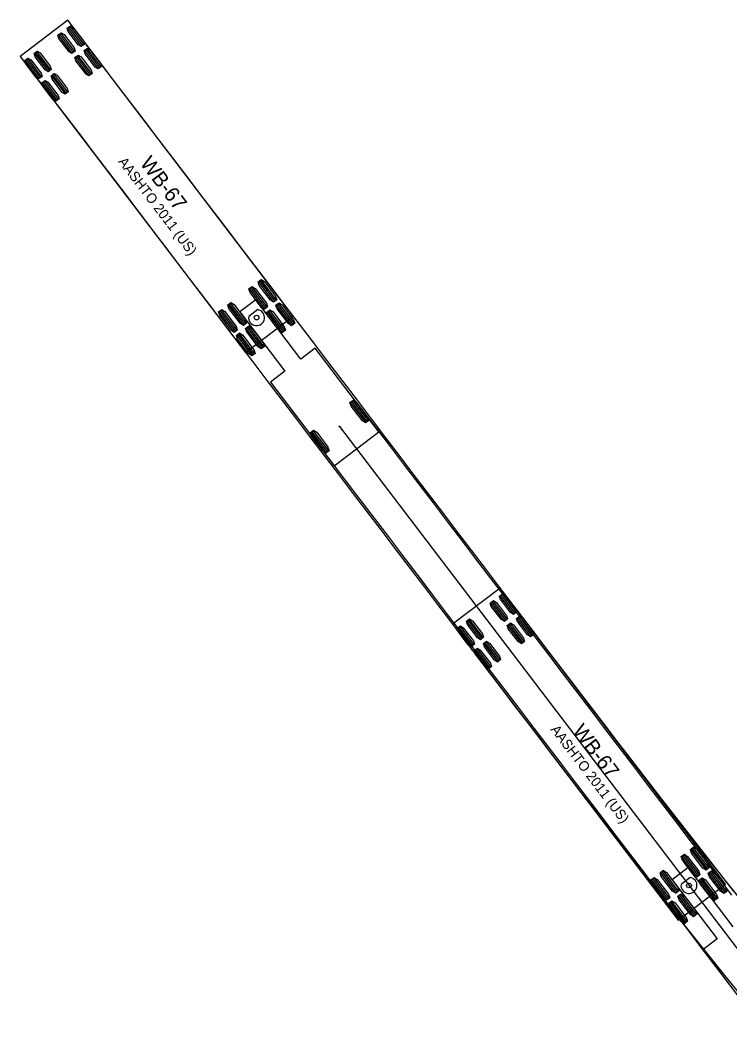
# Model space of a CAD drawing. Extents: x 916040 to 917457, y 328936 to 330267.
# Drawn here: x 916277.9 to 916379, y 330122.5 to 330266.8 of the extents above; entities that cross this region are included whole.
import ezdxf

# ---------------------------------------------------------------- set-up
doc = ezdxf.new("R2010")
doc.units = 0
for name, color, linetype in [('SB_LeftontoRoute25_WB67', 7, 'Continuous'), ('SB_RightontoRoute25_WB67_v2', 7, 'Continuous'), ('SB_ThruontonSacoRd_WB67', 7, 'Continuous')]:
    doc.layers.add(name, color=color, linetype=linetype)

msp = doc.modelspace()

# ---------------------------------------------------------------- linework, layer by layer
at = {"layer": 'SB_LeftontoRoute25_WB67'}
for p, q in [((916346.26, 330185.93), (916339.5, 330180.78)), ((916378.38, 330143.78), (916346.26, 330185.93)), ((916348.23, 330182.21), (916346.23, 330184.84)), ((916348.41, 330182.35), (916346.41, 330184.98)), ((916348.59, 330182.49), (916346.59, 330185.12)), ((916346.91, 330181.21), (916344.91, 330183.84)), ((916347.1, 330181.35), (916345.1, 330183.98)), ((916347.28, 330181.49), (916345.28, 330184.12)), ((916343.87, 330178.89), (916341.87, 330181.52)), ((916350.65, 330179.03), (916348.65, 330181.66)), ((916350.83, 330179.17), (916348.83, 330181.8)), ((916351.01, 330179.31), (916349.01, 330181.93)), ((916339.5, 330180.78), (916371.62, 330138.62)), ((916342.19, 330177.62), (916340.19, 330180.24)), ((916342.38, 330177.76), (916340.38, 330180.38)), ((916342.56, 330177.89), (916340.56, 330180.52)), ((916343.51, 330178.62), (916341.51, 330181.24)), ((916343.69, 330178.76), (916341.69, 330181.38)), ((916349.34, 330178.03), (916347.34, 330180.66)), ((916349.52, 330178.17), (916347.52, 330180.8)), ((916349.7, 330178.31), (916347.7, 330180.93)), ((916344.8, 330174.57), (916342.8, 330177.2)), ((916344.98, 330174.71), (916342.98, 330177.34)), ((916345.93, 330175.44), (916343.93, 330178.06)), ((916346.11, 330175.57), (916344.11, 330178.2)), ((916346.3, 330175.71), (916344.29, 330178.34)), ((916344.62, 330174.44), (916342.62, 330177.06)), ((916375.66, 330145.81), (916373.43, 330148.72)), ((916375.84, 330145.94), (916373.61, 330148.86)), ((916376.02, 330146.08), (916373.8, 330149)), ((916374.34, 330144.81), (916372.12, 330147.72)), ((916374.52, 330144.94), (916372.3, 330147.86)), ((916374.71, 330145.08), (916372.48, 330148)), ((916371.33, 330142.51), (916369.11, 330145.43)), ((916371.52, 330142.65), (916369.29, 330145.57)), ((916371.7, 330142.79), (916369.48, 330145.71)), ((916373.05, 330146.12), (916370.77, 330144.39)), ((916379.47, 330137.69), (916373.05, 330146.12)), ((916378.38, 330142.6), (916376.16, 330145.52)), ((916378.57, 330142.74), (916376.34, 330145.66)), ((916370.02, 330141.51), (916367.8, 330144.43)), ((916370.2, 330141.65), (916367.98, 330144.57)), ((916370.39, 330141.79), (916368.16, 330144.71)), ((916370.77, 330144.39), (916377.19, 330135.96)), ((916373.33, 330144.72), (916372.05, 330143.74)), ((916376.89, 330141.46), (916374.67, 330144.38)), ((916377.07, 330141.6), (916374.85, 330144.52)), ((916377.25, 330141.74), (916375.03, 330144.66)), ((916378.2, 330142.46), (916375.98, 330145.38)), ((916371.62, 330138.62), (916378.38, 330143.78)), ((916378.38, 330143.78), (916378.38, 330143.78)), ((916372.57, 330138.17), (916370.34, 330141.09)), ((916372.75, 330138.31), (916370.53, 330141.23)), ((916372.93, 330138.45), (916370.71, 330141.37)), ((916373.88, 330139.17), (916371.66, 330142.09)), ((916374.06, 330139.31), (916371.84, 330142.23)), ((916374.24, 330139.45), (916372.02, 330142.37)), ((916377.19, 330135.96), (916375.15, 330134.4)), ((916375.15, 330134.4), (916384.24, 330122.47))]:
    msp.add_line(p, q, dxfattribs=at)
for points in [[(916348.64, 330182.53), (916348.18, 330182.18), (916347.76, 330182.44), (916346.32, 330184.33), (916346.18, 330184.8), (916346.63, 330185.15), (916347.05, 330184.89), (916348.49, 330183)], [(916347.32, 330181.53), (916346.87, 330181.18), (916346.45, 330181.44), (916345.01, 330183.33), (916344.87, 330183.8), (916345.32, 330184.15), (916345.74, 330183.89), (916347.18, 330182)], [(916343.92, 330178.93), (916343.46, 330178.58), (916343.04, 330178.85), (916341.6, 330180.74), (916341.46, 330181.21), (916341.92, 330181.55), (916342.33, 330181.29), (916343.77, 330179.4)], [(916351.06, 330179.34), (916350.6, 330179), (916350.19, 330179.26), (916348.75, 330181.15), (916348.6, 330181.62), (916349.06, 330181.97), (916349.48, 330181.71), (916350.92, 330179.82)], [(916342.6, 330177.93), (916342.15, 330177.58), (916341.73, 330177.85), (916340.29, 330179.74), (916340.15, 330180.21), (916340.6, 330180.55), (916341.02, 330180.29), (916342.46, 330178.4)], [(916349.75, 330178.34), (916349.29, 330178), (916348.88, 330178.26), (916347.43, 330180.15), (916347.29, 330180.62), (916347.75, 330180.97), (916348.16, 330180.71), (916349.6, 330178.82)], [(916345.03, 330174.75), (916344.57, 330174.4), (916344.16, 330174.66), (916342.72, 330176.55), (916342.57, 330177.03), (916343.03, 330177.37), (916343.44, 330177.11), (916344.88, 330175.22)], [(916346.34, 330175.75), (916345.89, 330175.4), (916345.47, 330175.66), (916344.03, 330177.55), (916343.89, 330178.03), (916344.34, 330178.37), (916344.76, 330178.11), (916346.2, 330176.22)], [(916376.06, 330146.12), (916375.61, 330145.77), (916375.16, 330146.07), (916373.56, 330148.17), (916373.39, 330148.69), (916373.84, 330149.03), (916374.29, 330148.73), (916375.89, 330146.63)], [(916374.75, 330145.12), (916374.3, 330144.77), (916373.85, 330145.07), (916372.25, 330147.17), (916372.08, 330147.69), (916372.53, 330148.03), (916372.98, 330147.73), (916374.58, 330145.63)], [(916371.74, 330142.82), (916371.29, 330142.48), (916370.84, 330142.78), (916369.24, 330144.88), (916369.07, 330145.39), (916369.52, 330145.74), (916369.97, 330145.44), (916371.57, 330143.34)], [(916378.61, 330142.78), (916378.16, 330142.43), (916377.71, 330142.73), (916376.11, 330144.83), (916375.93, 330145.35), (916376.39, 330145.69), (916376.84, 330145.39), (916378.44, 330143.29)], [(916370.43, 330141.82), (916369.98, 330141.48), (916369.53, 330141.78), (916367.93, 330143.88), (916367.75, 330144.39), (916368.21, 330144.74), (916368.66, 330144.44), (916370.26, 330142.34)], [(916377.3, 330141.78), (916376.84, 330141.43), (916376.39, 330141.73), (916374.79, 330143.83), (916374.62, 330144.35), (916375.08, 330144.69), (916375.52, 330144.39), (916377.12, 330142.29)], [(916372.98, 330138.48), (916372.52, 330138.14), (916372.07, 330138.44), (916370.47, 330140.54), (916370.3, 330141.05), (916370.75, 330141.4), (916371.2, 330141.1), (916372.8, 330139)], [(916374.29, 330139.48), (916373.83, 330139.14), (916373.39, 330139.44), (916371.79, 330141.54), (916371.61, 330142.05), (916372.07, 330142.4), (916372.51, 330142.1), (916374.11, 330140)]]:
    msp.add_lwpolyline(points, close=True, dxfattribs=at)
for points in [[(916348.98, 330182.35), (916351.01, 330179.7), (916353.03, 330177.04), (916355.05, 330174.39), (916357.08, 330171.74), (916359.1, 330169.09), (916361.12, 330166.44), (916363.15, 330163.79), (916365.18, 330161.15), (916367.21, 330158.52), (916369.25, 330155.88), (916371.29, 330153.25), (916373.33, 330150.63), (916375.38, 330148.02), (916377.44, 330145.41), (916379.5, 330142.8)], [(916342.22, 330177.2), (916344.25, 330174.54), (916346.27, 330171.89), (916348.29, 330169.23), (916350.32, 330166.58), (916352.35, 330163.93), (916354.37, 330161.27), (916356.41, 330158.62), (916358.44, 330155.97), (916360.48, 330153.32), (916362.53, 330150.68), (916364.58, 330148.04), (916366.63, 330145.4), (916368.69, 330142.77), (916370.76, 330140.14), (916372.84, 330137.52), (916374.93, 330134.9), (916377.02, 330132.29), (916379.13, 330129.69)]]:
    msp.add_lwpolyline(points, dxfattribs=at)
for centre, radius in [((916348.98, 330182.35), 0.0417), ((916342.22, 330177.2), 0.0417), ((916373.18, 330143.59), 0.34)]:
    msp.add_circle(centre, radius, dxfattribs=at)
msp.add_arc((916373.18, 330143.59), 1.14, 172.3089, 82.3089, dxfattribs=at)
at = {"layer": 'SB_RightontoRoute25_WB67_v2'}
for p, q in [((916284.64, 330266.79), (916277.88, 330261.64)), ((916316.76, 330224.64), (916284.64, 330266.79)), ((916286.61, 330263.07), (916284.61, 330265.7)), ((916286.79, 330263.21), (916284.79, 330265.84)), ((916286.97, 330263.35), (916284.97, 330265.98)), ((916285.29, 330262.07), (916283.29, 330264.7)), ((916285.48, 330262.21), (916283.48, 330264.84)), ((916285.66, 330262.35), (916283.66, 330264.98)), ((916282.25, 330259.75), (916280.25, 330262.38)), ((916289.03, 330259.89), (916287.03, 330262.52)), ((916289.21, 330260.03), (916287.21, 330262.66)), ((916289.4, 330260.17), (916287.4, 330262.79)), ((916277.88, 330261.64), (916310, 330219.48)), ((916280.58, 330258.48), (916278.57, 330261.1)), ((916280.76, 330258.62), (916278.76, 330261.24)), ((916280.94, 330258.75), (916278.94, 330261.38)), ((916281.89, 330259.48), (916279.89, 330262.1)), ((916282.07, 330259.62), (916280.07, 330262.24)), ((916287.72, 330258.89), (916285.72, 330261.52)), ((916287.9, 330259.03), (916285.9, 330261.66)), ((916288.08, 330259.17), (916286.08, 330261.79)), ((916283.18, 330255.43), (916281.18, 330258.06)), ((916283.36, 330255.57), (916281.36, 330258.2)), ((916284.31, 330256.3), (916282.31, 330258.92)), ((916284.49, 330256.43), (916282.49, 330259.06)), ((916284.68, 330256.57), (916282.68, 330259.2)), ((916283, 330255.3), (916281, 330257.92)), ((916314.04, 330226.67), (916311.81, 330229.58)), ((916314.22, 330226.8), (916312, 330229.72)), ((916314.4, 330226.94), (916312.18, 330229.86)), ((916312.72, 330225.67), (916310.5, 330228.58)), ((916312.91, 330225.8), (916310.68, 330228.72)), ((916313.09, 330225.94), (916310.87, 330228.86)), ((916309.71, 330223.37), (916307.49, 330226.29)), ((916309.9, 330223.51), (916307.67, 330226.43)), ((916310.08, 330223.65), (916307.86, 330226.57)), ((916311.43, 330226.98), (916309.15, 330225.25)), ((916317.86, 330218.55), (916311.43, 330226.98)), ((916316.58, 330223.32), (916314.36, 330226.24)), ((916316.76, 330223.46), (916314.54, 330226.38)), ((916316.95, 330223.6), (916314.72, 330226.52)), ((916308.4, 330222.37), (916306.18, 330225.29)), ((916308.58, 330222.51), (916306.36, 330225.43)), ((916308.77, 330222.65), (916306.54, 330225.57)), ((916309.15, 330225.25), (916315.58, 330216.82)), ((916311.72, 330225.58), (916310.43, 330224.6)), ((916315.27, 330222.32), (916313.05, 330225.24)), ((916315.45, 330222.46), (916313.23, 330225.38)), ((916315.63, 330222.6), (916313.41, 330225.52)), ((916310, 330219.48), (916316.76, 330224.64)), ((916316.76, 330224.64), (916316.76, 330224.64)), ((916310.95, 330219.03), (916308.73, 330221.95)), ((916311.13, 330219.17), (916308.91, 330222.09)), ((916311.31, 330219.31), (916309.09, 330222.23)), ((916312.26, 330220.03), (916310.04, 330222.95)), ((916312.44, 330220.17), (916310.22, 330223.09)), ((916312.63, 330220.31), (916310.4, 330223.23)), ((916319.9, 330220.11), (916317.86, 330218.55)), ((916328.99, 330208.18), (916319.9, 330220.11)), ((916315.58, 330216.82), (916313.53, 330215.26)), ((916313.53, 330215.26), (916322.63, 330203.33)), ((916327.13, 330209.49), (916324.91, 330212.4)), ((916327.31, 330209.62), (916325.09, 330212.54)), ((916327.49, 330209.76), (916325.27, 330212.68)), ((916323.38, 330208.94), (916385, 330128.08)), ((916321.49, 330205.19), (916319.27, 330208.11)), ((916321.68, 330205.33), (916319.45, 330208.25)), ((916321.86, 330205.47), (916319.64, 330208.39)), ((916322.63, 330203.33), (916328.99, 330208.18)), ((916328.99, 330208.18), (916328.99, 330208.18))]:
    msp.add_line(p, q, dxfattribs=at)
for points in [[(916287.02, 330263.39), (916286.56, 330263.04), (916286.14, 330263.3), (916284.7, 330265.19), (916284.56, 330265.66), (916285.02, 330266.01), (916285.43, 330265.75), (916286.87, 330263.86)], [(916285.7, 330262.39), (916285.25, 330262.04), (916284.83, 330262.3), (916283.39, 330264.19), (916283.25, 330264.66), (916283.7, 330265.01), (916284.12, 330264.75), (916285.56, 330262.86)], [(916282.3, 330259.79), (916281.84, 330259.44), (916281.43, 330259.71), (916279.99, 330261.6), (916279.84, 330262.07), (916280.3, 330262.41), (916280.71, 330262.15), (916282.15, 330260.26)], [(916289.44, 330260.2), (916288.99, 330259.86), (916288.57, 330260.12), (916287.13, 330262.01), (916286.99, 330262.48), (916287.44, 330262.83), (916287.86, 330262.57), (916289.3, 330260.68)], [(916280.98, 330258.79), (916280.53, 330258.44), (916280.11, 330258.71), (916278.67, 330260.6), (916278.53, 330261.07), (916278.98, 330261.41), (916279.4, 330261.15), (916280.84, 330259.26)], [(916288.13, 330259.2), (916287.67, 330258.86), (916287.26, 330259.12), (916285.82, 330261.01), (916285.67, 330261.48), (916286.13, 330261.83), (916286.55, 330261.57), (916287.99, 330259.68)], [(916283.41, 330255.61), (916282.95, 330255.26), (916282.54, 330255.52), (916281.1, 330257.41), (916280.95, 330257.89), (916281.41, 330258.23), (916281.83, 330257.97), (916283.27, 330256.08)], [(916284.72, 330256.61), (916284.27, 330256.26), (916283.85, 330256.52), (916282.41, 330258.41), (916282.27, 330258.89), (916282.72, 330259.23), (916283.14, 330258.97), (916284.58, 330257.08)], [(916314.45, 330226.98), (916313.99, 330226.63), (916313.54, 330226.93), (916311.94, 330229.03), (916311.77, 330229.55), (916312.22, 330229.89), (916312.67, 330229.59), (916314.27, 330227.49)], [(916313.13, 330225.98), (916312.68, 330225.63), (916312.23, 330225.93), (916310.63, 330228.03), (916310.46, 330228.55), (916310.91, 330228.89), (916311.36, 330228.59), (916312.96, 330226.49)], [(916310.12, 330223.68), (916309.67, 330223.34), (916309.22, 330223.64), (916307.62, 330225.74), (916307.45, 330226.25), (916307.9, 330226.6), (916308.35, 330226.3), (916309.95, 330224.2)], [(916316.99, 330223.64), (916316.54, 330223.29), (916316.09, 330223.59), (916314.49, 330225.69), (916314.31, 330226.21), (916314.77, 330226.55), (916315.22, 330226.25), (916316.82, 330224.15)], [(916308.81, 330222.68), (916308.36, 330222.34), (916307.91, 330222.64), (916306.31, 330224.74), (916306.13, 330225.25), (916306.59, 330225.6), (916307.04, 330225.3), (916308.64, 330223.2)], [(916315.68, 330222.64), (916315.22, 330222.29), (916314.78, 330222.59), (916313.18, 330224.69), (916313, 330225.21), (916313.46, 330225.55), (916313.91, 330225.25), (916315.51, 330223.15)], [(916311.36, 330219.34), (916310.9, 330219), (916310.45, 330219.3), (916308.85, 330221.4), (916308.68, 330221.91), (916309.14, 330222.26), (916309.58, 330221.96), (916311.18, 330219.86)], [(916312.67, 330220.34), (916312.22, 330220), (916311.77, 330220.3), (916310.17, 330222.4), (916309.99, 330222.91), (916310.45, 330223.26), (916310.9, 330222.96), (916312.5, 330220.86)], [(916327.54, 330209.8), (916327.08, 330209.45), (916326.64, 330209.75), (916325.03, 330211.85), (916324.86, 330212.37), (916325.32, 330212.71), (916325.76, 330212.41), (916327.36, 330210.31)], [(916321.9, 330205.5), (916321.45, 330205.16), (916321, 330205.46), (916319.4, 330207.56), (916319.23, 330208.07), (916319.68, 330208.42), (916320.13, 330208.12), (916321.73, 330206.02)]]:
    msp.add_lwpolyline(points, close=True, dxfattribs=at)
for points in [[(916287.37, 330263.21), (916289.39, 330260.55), (916291.42, 330257.89), (916293.45, 330255.23), (916295.47, 330252.57), (916297.5, 330249.91), (916299.53, 330247.25), (916301.55, 330244.59), (916303.58, 330241.93), (916305.61, 330239.27), (916307.63, 330236.61), (916309.66, 330233.95), (916311.69, 330231.29), (916313.72, 330228.63), (916315.74, 330225.97), (916317.77, 330223.31), (916319.8, 330220.65), (916321.82, 330217.99), (916323.85, 330215.33), (916325.88, 330212.67), (916327.9, 330210.01), (916329.93, 330207.35), (916331.96, 330204.69), (916333.99, 330202.03), (916336.01, 330199.37), (916338.04, 330196.71), (916340.07, 330194.05), (916342.09, 330191.39), (916344.12, 330188.74), (916346.15, 330186.08), (916348.17, 330183.42), (916350.2, 330180.76), (916352.22, 330178.1), (916354.24, 330175.45), (916356.27, 330172.8), (916358.29, 330170.15), (916360.31, 330167.5), (916362.34, 330164.85), (916364.37, 330162.21), (916366.4, 330159.57), (916368.43, 330156.94), (916370.47, 330154.31), (916372.51, 330151.68), (916374.56, 330149.06), (916376.61, 330146.45), (916378.67, 330143.84), (916380.74, 330141.25)], [(916280.6, 330258.06), (916282.63, 330255.4), (916284.66, 330252.74), (916286.69, 330250.08), (916288.71, 330247.42), (916290.74, 330244.76), (916292.77, 330242.1), (916294.79, 330239.44), (916296.82, 330236.78), (916298.85, 330234.12), (916300.87, 330231.46), (916302.9, 330228.8), (916304.93, 330226.14), (916306.96, 330223.48), (916308.98, 330220.82), (916311.01, 330218.16), (916313.04, 330215.5), (916315.06, 330212.84), (916317.09, 330210.18), (916319.12, 330207.52), (916321.14, 330204.86), (916323.17, 330202.2), (916325.2, 330199.54), (916327.22, 330196.88), (916329.25, 330194.22), (916331.28, 330191.56), (916333.31, 330188.9), (916335.33, 330186.24), (916337.36, 330183.58), (916339.39, 330180.92), (916341.41, 330178.26), (916343.44, 330175.61), (916345.46, 330172.95), (916347.48, 330170.3), (916349.51, 330167.64), (916351.53, 330164.99), (916353.56, 330162.33), (916355.59, 330159.68), (916357.63, 330157.03), (916359.67, 330154.38), (916361.71, 330151.74), (916363.76, 330149.09), (916365.81, 330146.45), (916367.87, 330143.82), (916369.94, 330141.19), (916372.01, 330138.57), (916374.09, 330135.95), (916376.18, 330133.33), (916378.28, 330130.73), (916380.39, 330128.13)], [(916326.56, 330211.36), (916328.59, 330208.7), (916330.62, 330206.04), (916332.64, 330203.38), (916334.67, 330200.72), (916336.7, 330198.06), (916338.73, 330195.4), (916340.75, 330192.74), (916342.78, 330190.08), (916344.81, 330187.42), (916346.83, 330184.76), (916348.86, 330182.1), (916350.89, 330179.44), (916352.91, 330176.78), (916354.94, 330174.12), (916356.97, 330171.46), (916358.99, 330168.8), (916361.02, 330166.14), (916363.05, 330163.48), (916365.08, 330160.82), (916367.1, 330158.16), (916369.13, 330155.5), (916371.16, 330152.84), (916373.18, 330150.18), (916375.21, 330147.52), (916377.24, 330144.86), (916379.26, 330142.2)], [(916320.2, 330206.51), (916322.23, 330203.85), (916324.25, 330201.19), (916326.28, 330198.53), (916328.31, 330195.87), (916330.34, 330193.21), (916332.36, 330190.55), (916334.39, 330187.89), (916336.42, 330185.23), (916338.44, 330182.57), (916340.47, 330179.91), (916342.5, 330177.25), (916344.52, 330174.59), (916346.55, 330171.93), (916348.58, 330169.27), (916350.6, 330166.61), (916352.63, 330163.95), (916354.66, 330161.29), (916356.69, 330158.63), (916358.71, 330155.97), (916360.74, 330153.31), (916362.77, 330150.65), (916364.79, 330147.99), (916366.82, 330145.33), (916368.85, 330142.67), (916370.87, 330140.01), (916372.9, 330137.35), (916374.93, 330134.69), (916376.96, 330132.04), (916378.98, 330129.38), (916381.01, 330126.72)]]:
    msp.add_lwpolyline(points, dxfattribs=at)
for centre, radius in [((916287.37, 330263.21), 0.0417), ((916280.6, 330258.06), 0.0417), ((916311.56, 330224.45), 0.34), ((916326.56, 330211.36), 0.0417), ((916323.38, 330208.94), 0.0417), ((916320.2, 330206.51), 0.0417)]:
    msp.add_circle(centre, radius, dxfattribs=at)
msp.add_arc((916311.56, 330224.45), 1.14, 172.3089, 82.3089, dxfattribs=at)
at = {"layer": 'SB_ThruontonSacoRd_WB67'}
msp.add_line((916323.38, 330208.94), (916385, 330128.08), dxfattribs=at)

# ---------------------------------------------------------------- texts
at = {"layer": 'SB_LeftontoRoute25_WB67'}
for s, height, p in [('AASHTO 2011 (US)', 1.4167, (916353.38, 330165.78)), ('WB-67', 2.125, (916356.45, 330165.54))]:
    msp.add_text(s, height=height, rotation=307.3089, dxfattribs=at).set_placement(p)
at = {"layer": 'SB_RightontoRoute25_WB67_v2'}
for s, height, p in [('AASHTO 2011 (US)', 1.4167, (916291.76, 330246.64)), ('WB-67', 2.125, (916294.84, 330246.4))]:
    msp.add_text(s, height=height, rotation=307.3089, dxfattribs=at).set_placement(p)

doc.saveas('drawing.dxf')
